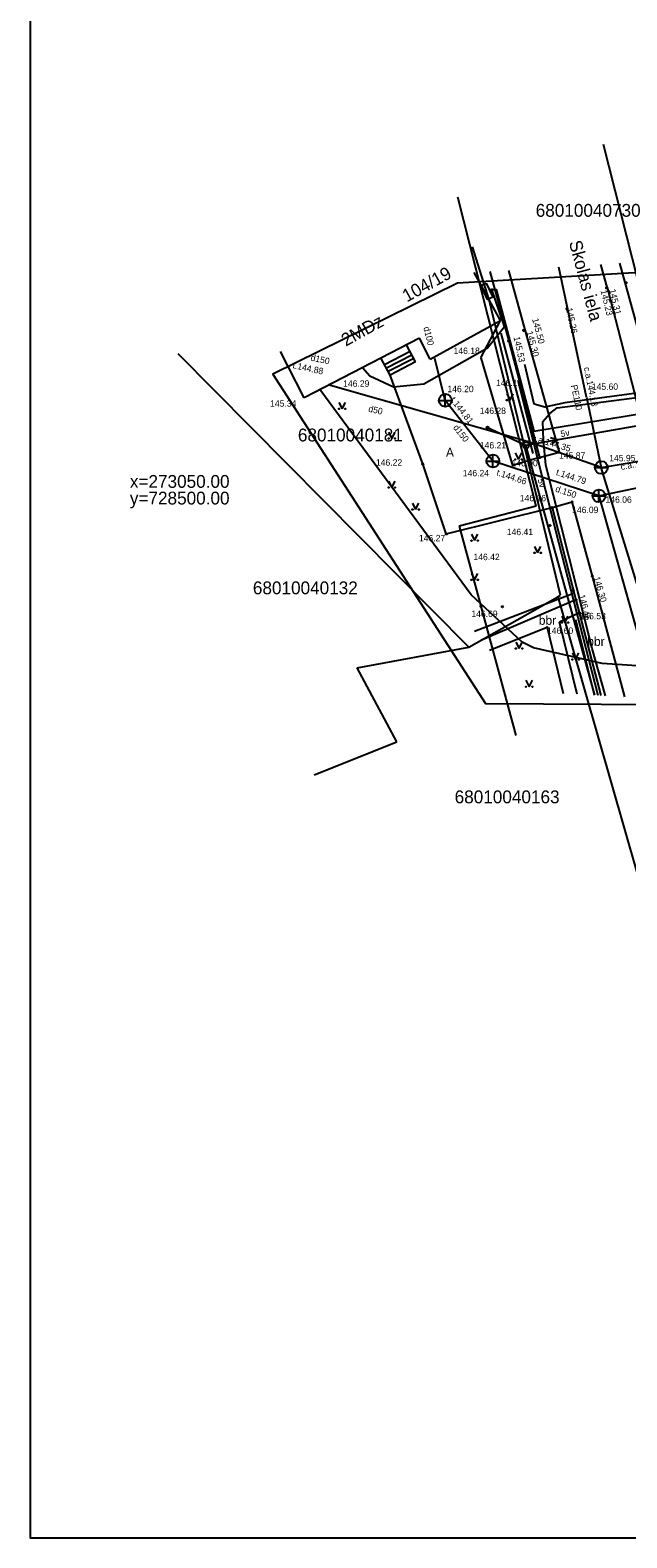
# Model space of a CAD drawing. Extents: x 728492 to 729038, y 272968 to 273171.
# Drawn here: x 728492.2 to 728538.7, y 272968.3 to 273085.8 of the extents above; entities that cross this region are included whole.
import ezdxf

# ---------------------------------------------------------------- set-up
doc = ezdxf.new("R2010")
doc.units = 0
for name, color, linetype in [('APGR_SARK_####_####_#', 7, 'Continuous'), ('BUVE_BDET_####_####_#', 7, 'Continuous'), ('BUVE_EKAS_####_####_#', 7, 'Continuous'), ('BUVE_EKAS_ADRS_TKST_#', 7, 'Continuous'), ('BUVE_EKAS_RAKS_TKST_#', 7, 'Continuous'), ('CELI_CAPM_####_####_#', 7, 'Continuous'), ('CELI_CMAL_####_####_#', 7, 'Continuous'), ('CELI_CSEG_####_TKST_#', 7, 'Continuous'), ('CELI_IELA_####_TKST_#', 7, 'Continuous'), ('CELI_SEGL_####_####_#', 7, 'Continuous'), ('ELEK_ELEM_####_####_#', 7, 'Continuous'), ('ELEK_SAVL_####_####_#', 7, 'Continuous'), ('ELEK_VADP_VSPR_####_#', 7, 'Continuous'), ('ELEK_VADP_ZSPR_####_#', 7, 'Continuous'), ('ELEK_VADV_ZSPR_####_#', 7, 'Continuous'), ('ELEK_VADV_ZSPR_TKST_#', 7, 'Continuous'), ('GEOD_KORD_####_TKST_#', 7, 'Continuous'), ('Level 18', 7, 'Continuous'), ('RAMI_PLAN_####_TKST_#', 7, 'Continuous'), ('RAMI_UZMR_####_####_#', 7, 'Continuous'), ('RELJ_AATZ_####_TKST_#', 7, 'Continuous'), ('RELJ_ELEM_####_####_#', 7, 'Continuous'), ('ROBZ_KADS_####_TKST_#', 7, 'Continuous'), ('ROBZ_UZMR_####_####_#', 7, 'Continuous'), ('SAKT_VADP_KABE_####_#', 7, 'Continuous'), ('SILT_ELEM_####_TKST_#', 7, 'Continuous'), ('SKAN_ELEM_####_####_#', 7, 'Continuous'), ('SKAN_ELEM_PAST_TKST_#', 7, 'Continuous'), ('SKAN_VADP_PAST_####_#', 7, 'Continuous'), ('SKAN_VADP_PAST_TKST_#', 7, 'Continuous'), ('TERT_DZOG_####_####_#', 7, 'Continuous'), ('TERT_ELEM_####_####_#', 7, 'Continuous'), ('UDTK_ELEM_####_####_#', 7, 'Continuous'), ('UDTK_ELEM_####_TKST_#', 7, 'Continuous'), ('UDTK_VADP_UDEN_####_#', 7, 'Continuous'), ('UDTK_VADP_UDEN_TKST_#', 7, 'Continuous')]:
    doc.layers.add(name, color=color, linetype=linetype)

msp = doc.modelspace()

# ---------------------------------------------------------------- linework, layer by layer
at = {"layer": 'APGR_SARK_####_####_#'}
msp.add_line((728531.68, 273048.71), (728525.68, 273047.15), dxfattribs=at)
for points in [[(728541.41, 273059.19), (728536.92, 273076.93)], [(728531.68, 273048.71), (728525.58, 273072.82)], [(728525.68, 273047.15), (728530.09, 273030.84)]]:
    msp.add_lwpolyline(points, dxfattribs=at)
at = {"layer": 'BUVE_BDET_####_####_#'}
for p, q in [((728521.85, 273060.77), (728519.86, 273059.74)), ((728521.99, 273060.5), (728520, 273059.48)), ((728522.26, 273059.97), (728521.57, 273061.31)), ((728520.28, 273058.94), (728519.6, 273060.24)), ((728522.13, 273060.24), (728520.14, 273059.21)), ((728522.26, 273059.97), (728520.28, 273058.94))]:
    msp.add_line(p, q, dxfattribs=at)
at = {"layer": 'BUVE_EKAS_####_####_#'}
for p, q in [((728528.89, 273063.2), (728526.83, 273066.93)), ((728523.42, 273060.18), (728528.89, 273063.2)), ((728522.57, 273061.83), (728513.58, 273057.18)), ((728523.42, 273060.18), (728522.57, 273061.83)), ((728513.58, 273057.18), (728511.74, 273060.79))]:
    msp.add_line(p, q, dxfattribs=at)
at = {"layer": 'CELI_CAPM_####_####_#'}
for q in [(728536.72, 273067.57), (728539.78, 273055.81)]:
    msp.add_line((728537.21, 273065.79), q, dxfattribs=at)
msp.add_lwpolyline([(728529.53, 273067.11), (728530.79, 273062.47), (728533.46, 273052.93)], dxfattribs=at)
at = {"layer": 'CELI_CMAL_####_####_#'}
for p, q in [((728541.62, 273055.23), (728538.21, 273067.67)), ((728527.37, 273060.29), (728529.82, 273051.89)), ((728522.83, 273052.01), (728520.28, 273058.94)), ((728531.94, 273052.51), (728529.82, 273051.89)), ((728524.67, 273046.55), (728532.91, 273048.61)), ((728532.91, 273048.61), (728532.91, 273048.61)), ((728532.52, 273039.26), (728533.79, 273034.12)), ((728534.87, 273034.06), (728533.49, 273039.68))]:
    msp.add_line(p, q, dxfattribs=at)
for points in [[(728528.07, 273067.01), (728529.54, 273061.6), (728531.94, 273052.51)], [(728527.37, 273060.29), (728528.89, 273063.2)], [(728524.67, 273046.55), (728524.67, 273046.55), (728522.83, 273052.01)], [(728532.91, 273048.61), (728534.78, 273041.41), (728536.72, 273033.95)], [(728538.58, 273033.85), (728536.06, 273043.26), (728534.48, 273049.06)], [(728534.78, 273041.41), (728527.41, 273038.26)], [(728535.05, 273040.39), (728533.49, 273039.68)], [(728532.52, 273039.26), (728528.03, 273037.46)]]:
    msp.add_lwpolyline(points, dxfattribs=at)
at = {"layer": 'CELI_SEGL_####_####_#'}
for p, q in [((728531.94, 273052.51), (728533.46, 273052.93)), ((728532.91, 273048.61), (728534.48, 273049.06))]:
    msp.add_line(p, q, dxfattribs=at)
at = {"layer": 'ELEK_ELEM_####_####_#'}
msp.add_lwpolyline([(728527.78, 273066.12), (728528.29, 273065.03), (728527.89, 273064.84), (728527.38, 273065.92)], close=True, dxfattribs=at)
for centre, radius in [((728527.88, 273054.86), 0.075), ((728530.88, 273053.47), 0.25)]:
    msp.add_circle(centre, radius, dxfattribs=at)
at = {"layer": 'ELEK_SAVL_####_####_#'}
for p, q in [((728527.88, 273054.86), (728530.88, 273053.47)), ((728536.25, 273033.98), (728530.88, 273053.47)), ((728533.34, 273053.9), (728531.12, 273053.51)), ((728533.34, 273053.9), (728532.8, 273054.06)), ((728533.34, 273053.9), (728532.89, 273053.57))]:
    msp.add_line(p, q, dxfattribs=at)
at = {"layer": 'ELEK_VADP_VSPR_####_#'}
for points in [[(728528.24, 273065.61), (728528.56, 273065.61), (728531.5, 273054.57), (728567.06, 273060.41)], [(728536.51, 273033.96), (728533.43, 273045.88), (728532.42, 273049.91), (728530.26, 273058.51)]]:
    msp.add_lwpolyline(points, dxfattribs=at)
at = {"layer": 'ELEK_VADP_ZSPR_####_#'}
for points in [[(728537.08, 273033.93), (728536.03, 273037.61), (728532.42, 273051.93), (728532.25, 273053.87), (728532.2, 273055.31), (728532.73, 273055.95), (728533.31, 273056.4), (728544.74, 273057.86), (728548.08, 273058.29), (728556.86, 273059.59), (728568.23, 273061.28), (728585.45, 273064.11), (728594.55, 273065.6), (728599.54, 273066.28), (728606.83, 273067.28), (728608.39, 273067.73), (728608.81, 273068.92), (728608.81, 273069.37), (728608.94, 273077.26)], [(728518.13, 273059.53), (728518.72, 273058.89), (728520.56, 273058.02), (728522.92, 273058.25), (728527.88, 273061.07), (728529.21, 273062.72), (728528.19, 273065.69)], [(728567.75, 273060.11), (728567.41, 273060.75), (728567.07, 273061.01), (728566.66, 273061.21), (728566.41, 273061.34), (728554.03, 273059.5), (728551.7, 273059.16), (728548.18, 273058.69), (728544.32, 273058.17), (728533.92, 273056.79), (728532.35, 273056.44), (728531.53, 273056.67), (728530.78, 273059.78)]]:
    msp.add_lwpolyline(points, dxfattribs=at)
at = {"layer": 'ELEK_VADV_ZSPR_####_#'}
msp.add_line((728530.88, 273053.47), (728577.71, 273061.66), dxfattribs=at)
at = {"layer": 'Level 18'}
msp.add_circle((728527.88, 273054.86), 0.075, dxfattribs=at)
at = {"layer": 'RAMI_PLAN_####_TKST_#'}
msp.add_lwpolyline([(728492.23, 273152.29), (728492.23, 272968.26), (728765.31, 272968.26), (728765.31, 273152.29)], close=True, dxfattribs=at)
at = {"layer": 'RAMI_UZMR_####_####_#'}
msp.add_lwpolyline([(728545.12, 273067.26), (728525.54, 273066.11), (728511.14, 273059.02), (728527.73, 273033.33), (728550.27, 273033.2), (728572.01, 273034.89), (728580.56, 273045.27), (728653.67, 273058.93), (728671.71, 273053.29), (728688.72, 273058.41), (728702.15, 273066.92)], dxfattribs=at)
at = {"layer": 'RELJ_ELEM_####_####_#'}
for centre in [(728538.69, 273066.15), (728537.18, 273065.74), (728534.08, 273064.12), (728529.54, 273061.6), (728530.7, 273062.43), (728522.83, 273052.01), (728531.94, 273052.51), (728533.45, 273052.93), (728536.75, 273051.73), (728532.91, 273048.61), (728534.48, 273049.06), (728536.57, 273049.52), (728524.67, 273046.55), (728532.75, 273047.21), (728536.06, 273043.26), (728534.56, 273042.15), (728534.78, 273041.41), (728527.38, 273040.9), (728529.04, 273040.88), (728535.06, 273040.4), (728532.52, 273039.26)]:
    msp.add_circle(centre, 0.05, dxfattribs=at)
at = {"layer": 'ROBZ_UZMR_####_####_#'}
for p, q in [((728528.02, 273064.82), (728526.72, 273068.95)), ((728533.58, 273041.78), (728528.02, 273064.82)), ((728526.42, 273037.73), (728503.77, 273060.6)), ((728526.42, 273037.73), (728533.37, 273041.66)), ((728533.37, 273041.66), (728533.58, 273041.78)), ((728533.37, 273041.66), (728539.61, 273019.88)), ((728517.72, 273036.1), (728526.42, 273037.73)), ((728520.81, 273030.34), (728517.72, 273036.1)), ((728514.37, 273027.77), (728520.81, 273030.34))]:
    msp.add_line(p, q, dxfattribs=at)
at = {"layer": 'SAKT_VADP_KABE_####_#'}
msp.add_lwpolyline([(728549.13, 273037.47), (728545.34, 273035.87), (728536.82, 273036.46), (728531.46, 273037.66), (728530.59, 273038.12), (728526.6, 273041.81), (728514.8, 273057.81)], dxfattribs=at)
at = {"layer": 'SKAN_ELEM_####_####_#'}
for p, q in [((728524.09, 273056.97), (728525.09, 273056.97)), ((728524.59, 273056.47), (728524.59, 273057.47)), ((728527.8, 273052.24), (728528.8, 273052.24)), ((728528.3, 273051.74), (728528.3, 273052.74)), ((728536.57, 273049.02), (728536.57, 273050.02)), ((728536.07, 273049.52), (728537.07, 273049.52))]:
    msp.add_line(p, q, dxfattribs=at)
for centre in [(728524.59, 273056.97), (728528.3, 273052.24), (728536.57, 273049.52)]:
    msp.add_circle(centre, 0.5, dxfattribs=at)
at = {"layer": 'SKAN_VADP_PAST_####_#'}
for points in [[(728536.57, 273049.52), (728528.3, 273052.24), (728524.59, 273056.97), (728523.77, 273060.23)], [(728536.57, 273049.52), (728565.94, 273055.68), (728568.91, 273039.47), (728569.27, 273036.19)], [(728536.57, 273049.52), (728541, 273033.71)]]:
    msp.add_lwpolyline(points, dxfattribs=at)
at = {"layer": 'TERT_DZOG_####_####_#'}
for points in [[(728528.91, 273062.21), (728531.41, 273052.82)], [(728526.86, 273038.97), (728534.59, 273041.93)], [(728536.22, 273033.98), (728534.78, 273039.86)]]:
    msp.add_lwpolyline(points, dxfattribs=at)
at = {"layer": 'TERT_ELEM_####_####_#'}
for p, q in [((728516.3, 273056.81), (728516.55, 273056.31)), ((728516.55, 273056.31), (728516.8, 273056.81)), ((728529.39, 273057.48), (728529.64, 273056.98)), ((728529.64, 273056.98), (728529.89, 273057.48)), ((728520.17, 273054.5), (728520.42, 273054)), ((728520.42, 273054), (728520.67, 273054.5)), ((728530.05, 273052.87), (728530.3, 273052.37)), ((728530.3, 273052.37), (728530.55, 273052.87)), ((728520.17, 273050.67), (728520.42, 273050.17)), ((728520.42, 273050.17), (728520.67, 273050.67)), ((728522.03, 273048.96), (728522.28, 273048.46)), ((728522.28, 273048.46), (728522.53, 273048.96)), ((728526.63, 273046.53), (728526.88, 273046.03)), ((728526.88, 273046.03), (728527.13, 273046.53)), ((728531.54, 273045.58), (728531.79, 273045.08)), ((728531.79, 273045.08), (728532.04, 273045.58)), ((728526.63, 273043.48), (728526.88, 273042.98)), ((728526.88, 273042.98), (728527.13, 273043.48)), ((728533.67, 273040.14), (728533.92, 273039.64)), ((728533.92, 273039.64), (728534.17, 273040.14)), ((728530.09, 273038.12), (728530.34, 273037.62)), ((728530.34, 273037.62), (728530.59, 273038.12)), ((728534.5, 273037.27), (728534.75, 273036.77)), ((728534.75, 273036.77), (728535, 273037.27)), ((728530.88, 273035.14), (728531.13, 273034.64)), ((728531.13, 273034.64), (728531.38, 273035.14))]:
    msp.add_line(p, q, dxfattribs=at)
for centre, radius in [((728529.39, 273056.98), 0.028), ((728529.89, 273056.98), 0.0263), ((728516.3, 273056.31), 0.028), ((728516.8, 273056.31), 0.0263), ((728520.17, 273054), 0.028), ((728520.67, 273054), 0.0263), ((728530.05, 273052.37), 0.028), ((728530.55, 273052.37), 0.0263), ((728520.17, 273050.17), 0.028), ((728520.67, 273050.17), 0.0263), ((728522.03, 273048.46), 0.028), ((728522.53, 273048.46), 0.0263), ((728526.63, 273046.03), 0.028), ((728527.13, 273046.03), 0.0263), ((728531.54, 273045.08), 0.028), ((728532.04, 273045.08), 0.0263), ((728526.63, 273042.98), 0.028), ((728527.13, 273042.98), 0.0263), ((728533.67, 273039.64), 0.028), ((728534.17, 273039.64), 0.0263), ((728530.09, 273037.62), 0.028), ((728530.59, 273037.62), 0.0263), ((728534.5, 273036.76), 0.028), ((728535, 273036.76), 0.0263), ((728530.88, 273034.64), 0.028), ((728531.38, 273034.64), 0.0263)]:
    msp.add_circle(centre, radius, dxfattribs=at)
at = {"layer": 'UDTK_ELEM_####_####_#'}
msp.add_line((728536.25, 273051.73), (728537.25, 273051.73), dxfattribs=at)
msp.add_circle((728536.75, 273051.73), 0.5, dxfattribs=at)
at = {"layer": 'UDTK_VADP_UDEN_####_#'}
for p, q in [((728535.6, 273057.21), (728533.45, 273067.36)), ((728535.6, 273057.21), (728536.75, 273051.73)), ((728542.3, 273033.64), (728536.75, 273051.73))]:
    msp.add_line(p, q, dxfattribs=at)
for points in [[(728536.75, 273051.73), (728562.04, 273055.95), (728585.76, 273058.37), (728605.4, 273061.62), (728606.94, 273061.77), (728607.47, 273061.9), (728613.69, 273063.02), (728614.11, 273063.01), (728657.44, 273069.24)], [(728536.75, 273051.73), (728531.15, 273053.7), (728515.45, 273058.19)]]:
    msp.add_lwpolyline(points, dxfattribs=at)

# ---------------------------------------------------------------- texts
at = {"layer": 'BUVE_EKAS_ADRS_TKST_#'}
msp.add_text('104/19', height=1, rotation=28.892, dxfattribs=at).set_placement((728521.59, 273064.6))
at = {"layer": 'BUVE_EKAS_RAKS_TKST_#'}
msp.add_text('2MDz', height=1, rotation=28.892, dxfattribs=at).set_placement((728516.83, 273061.15))
at = {"layer": 'CELI_CSEG_####_TKST_#'}
for s, p in [('A', (728524.64, 273052.57)), ('bbr', (728531.88, 273039.47)), ('bbr', (728535.66, 273037.82))]:
    msp.add_text(s, height=0.7, dxfattribs=at).set_placement(p)
at = {"layer": 'CELI_IELA_####_TKST_#'}
msp.add_text('Skolas iela', height=1, rotation=285.14, dxfattribs=at).set_placement((728534.22, 273069.3))
at = {"layer": 'ELEK_VADV_ZSPR_TKST_#'}
for rotation, p in [(9.9225, (728533.62, 273054.1)), (285.4163, (728531.77, 273050.79))]:
    msp.add_text('5v', height=0.5, rotation=rotation, dxfattribs=at).set_placement(p)
at = {"layer": 'GEOD_KORD_####_TKST_#'}
for s, p in [('x=273050.00', (728500, 273050.15)), ('y=728500.00', (728500, 273048.85))]:
    msp.add_text(s, height=1, dxfattribs=at).set_placement(p)
at = {"layer": 'RELJ_AATZ_####_TKST_#'}
for s, rotation, p in [('145.23', 283.9099, (728536.69, 273065.52)), ('145.31', 283.485, (728537.36, 273065.59)), ('145.26', 282.2815, (728533.99, 273064.14)), ('145.50', 285.0346, (728531.35, 273063.31)), ('145.53', 282.3096, (728529.91, 273061.9)), ('145.30', 285.0425, (728530.91, 273062.31)), ('146.30', 286.1008, (728536.15, 273043.15)), ('146.46', 284.8148, (728534.98, 273041.75))]:
    msp.add_text(s, height=0.5, rotation=rotation, dxfattribs=at).set_placement(p)
for s, p in [(' 146.18', (728525.05, 273060.59)), (' 146.29', (728516.44, 273058.03)), (' 146.11', (728528.36, 273058.08)), (' 145.60', (728535.83, 273057.79)), (' 145.34', (728510.75, 273056.48)), (' 146.28', (728527.09, 273055.91)), (' 146.21', (728527.1, 273053.22)), (' 146.22', (728519, 273051.88)), ('146.00', (728529.75, 273051.82)), ('145.87', (728533.46, 273052.43)), ('146.16', (728530.4, 273049.1)), ('146.09', (728534.48, 273048.18)), (' 146.27', (728522.35, 273045.98)), (' 146.41', (728529.2, 273046.46)), (' 146.69', (728526.44, 273040.08)), ('146.53', (728535.06, 273039.9)), ('146.60', (728532.52, 273038.76))]:
    msp.add_text(s, height=0.5, dxfattribs=at).set_placement(p)
at = {"layer": 'ROBZ_KADS_####_TKST_#'}
for s, p in [('68010040730', (728531.64, 273071.29)), ('68010040181', (728513.1, 273053.77)), ('68010040132', (728509.59, 273041.85)), ('68010040163', (728525.32, 273025.55))]:
    msp.add_text(s, height=1, dxfattribs=at).set_placement(p)
at = {"layer": 'SILT_ELEM_####_TKST_#'}
msp.add_text(' 146.42', height=0.5, dxfattribs=at).set_placement((728526.6, 273044.51))
at = {"layer": 'SKAN_ELEM_####_####_#'}
msp.add_text('146.06', height=0.5, dxfattribs=at).set_placement((728537.08, 273048.98))
at = {"layer": 'SKAN_ELEM_PAST_TKST_#'}
for s, p in [(' 146.20', (728524.57, 273057.61)), (' 146.24', (728525.77, 273051.05))]:
    msp.add_text(s, height=0.5, dxfattribs=at).set_placement(p)
at = {"layer": 'SKAN_VADP_PAST_TKST_#'}
for s, rotation, p in [('d100', 284.231, (728522.88, 273062.65)), ('d150', 347.837, (728514.06, 273060.08)), ('t.144.88', 347.837, (728512.66, 273059.49)), ('t.144.81', 308.071, (728524.95, 273056.99)), ('d150', 308.071, (728525.17, 273054.84)), ('t.144.66', 341.814, (728528.54, 273051.14)), ('t.144.79', 341.814, (728533.18, 273051.16)), ('d.150', 341.182, (728533.13, 273049.87))]:
    msp.add_text(s, height=0.5, rotation=rotation, dxfattribs=at).set_placement(p)
at = {"layer": 'UDTK_ELEM_####_TKST_#'}
msp.add_text('145.95', height=0.5, dxfattribs=at).set_placement((728537.37, 273052.22))
at = {"layer": 'UDTK_VADP_UDEN_TKST_#'}
for s, rotation, p in [('c.a.144.13', 281.493, (728535.38, 273059.52)), ('PE110', 281.931, (728534.38, 273058.13)), ('d50', 347.816, (728518.56, 273056.09)), ('c.a.144.35', 343.2851, (728531.29, 273053.85)), ('c.a.144.00', 10.8909, (728538.31, 273051.53))]:
    msp.add_text(s, height=0.5, rotation=rotation, dxfattribs=at).set_placement(p)

doc.saveas('drawing.dxf')
